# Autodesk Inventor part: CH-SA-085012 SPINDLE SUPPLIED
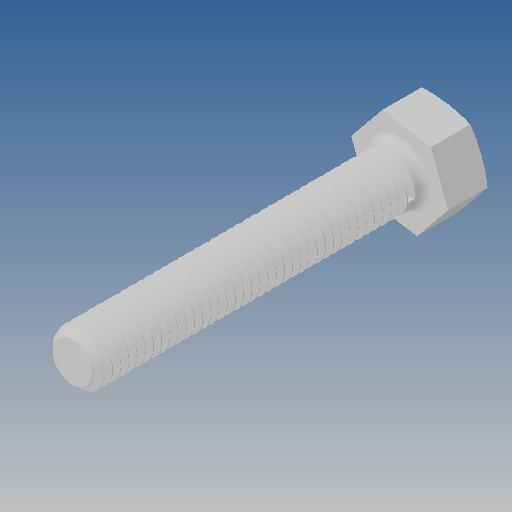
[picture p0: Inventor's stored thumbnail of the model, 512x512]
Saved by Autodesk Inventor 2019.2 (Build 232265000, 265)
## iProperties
Created: 2013-03
Part Number: CH-SA-085012 SPINDLE SUPPLIED
Material: Ogólny
Document SubType Name: Modeling
Designer: CADENGINEERING4
Density: 1 g/cm^3
Appearance: Domyślna
Author: CADENGINEERING4
Revision Number: ÈÎºÎ
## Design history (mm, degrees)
feature "ÇÐ³ý-É¨Ãè1"
node "Bryła1"
